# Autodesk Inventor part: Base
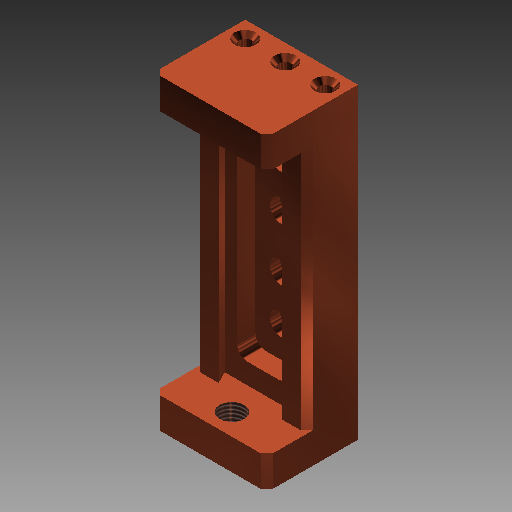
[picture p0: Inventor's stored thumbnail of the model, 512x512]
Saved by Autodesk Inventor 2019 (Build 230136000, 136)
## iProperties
Created: 2011-02
Part Number: Base
Material: Generic
Document SubType Name: Modeling
Designer: landrews
Density: 1 g/cm^3
Appearance: Copper - Polished
Mass: 182.26 g
Surface Area: 402.174 cm^2
Volume: 182.26 cm^3
Author: landrews
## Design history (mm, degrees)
sketch "Sketch1"
  geometry: L1 (-27.5, 12.5)-(27.5, 12.5); L2 (27.5, 12.5)-(27.5, 37.5); L3 (27.5, 37.5)-(15.5, 37.5); L4 (15.5, 37.5)-(18.5, 31.5); L5 (18.5, 31.5)-(-18.5, 31.5); L6 (-18.5, 31.5)-(-15.5, 37.5); L7 (-15.5, 37.5)-(-27.5, 37.5); L8 (-27.5, 37.5)-(-27.5, 12.5); L9 (0, 7.5)-(0, 42.5) reference; L10 (-38.5, 12.5)-(38.5, 12.5) reference; 2 further points
  constraints: 16 end point, 4 parallel, 2 equal length, 2 midpoint, 1 coincident, 1 collinear, 1 horizontal, 1 perpendicular, 1 other
  dimensions: "Base_Width" = 55 distance of L1.start L1.end; "Base_Height" = 25 distance of L1.end L2.end; "Slider_Shelf" = 12 distance of L2.end L3.end; "d3" = 9 horizontal distance of L2.end L4.end (computed from Slider_Shelf); "d2" = 6 distance between parallel lines of L3 L5
extrude "Extrusion1" new body sketch "Sketch1" taper "d8" = 0 deg; stored distance "Base_Length" = 120
sketch "Sketch4"
  geometry: L1 (11, -110)-(26, -110); L2 (31, -105)-(31, -15); L3 (26, -10)-(11, -10); L4 (6, -15)-(6, -105); L5 (-20, -60)-(57, -60) reference; L6 (18.5, 24)-(18.5, -144) reference; L7 (-9, -120)-(-9, 0) reference; L8 (37, 0)-(0, 0) reference; A1 r 5 centre (11, -105) between (6, -105) and (11, -110); A2 r 5 centre (26, -105) between (26, -110) and (31, -105); A3 r 5 centre (26, -15) between (31, -15) and (26, -10); A4 r 5 centre (11, -15) between (11, -10) and (6, -15)
  constraints: 8 end point, 8 point on circle, 8 tangent, 4 centre point, 3 equal radius, 2 parallel, 1 horizontal, 1 perpendicular, 2 other
  dimensions: "StopPlate_DP" = 5 radius of A1; "d25" = 100 distance between parallel lines of L1 L3 (computed from Base_Length); "d26" = 25 distance between parallel lines of L2 L4 (computed from Base_Width)
extrude "Extrusion2" cut sketch "Sketch4" extent not by distance; stored distance "d23" = 10; taper "d24" = 0 deg
sketch "Sketch6"
  geometry: L1 (27.5, 37.5)-(27.5, 12.5) reference; L2 (-27.5, 12.5)-(27.5, 12.5); L3 (27.5, 12.5)-(27.5, 57); L4 (27.5, 57)-(-27.5, 57); L5 (-27.5, 57)-(-27.5, 12.5); 1 further point
  constraints: 8 end point, 2 parallel, 1 horizontal, 1 perpendicular, 1 point on line
  dimensions: "EndBlock_HT" = 44.5 distance between parallel lines of L2 L4
extrude "Extrusion4" join sketch "Sketch6" taper "d38" = 0 deg; distance "EndBlock_DP" = 15
mirror "Mirror1"
sketch "Sketch7"
  geometry: L1 (-27.5, 57)-(27.5, 57) reference; L2 (0, 65.9)-(0, 3.6) reference; 2 further points
  constraints: 1 point on line
  dimensions: "d39" = 10.5 distance from line of point (0, 46.5) L1
hole "Hole1" sketch "Sketch7" at (0, 46.5) diameter "d40" = 12; stored, may be unused: countersink angle "d44" = 90 deg, drill point angle "d46" = 118 deg; dims "d41" = 6, "d42" = 4, "d43" = 2, "d45" = 8
sketch "Sketch14"
  geometry: L1 (27.5, 12.5)-(-27.5, 12.5) reference; L2 (0, 65.9)-(0, 3.6) reference; 2 further points
  constraints: 1 point on line
  dimensions: "d83" = 8 distance from line of L1 point (0, 20.5)
hole "Hole5" sketch "Sketch14" at (0, 20.5) diameter "d84" = 6; stored, may be unused: countersink angle "d88" = 90 deg, drill point angle "d90" = 118 deg; dims "d85" = 6, "d86" = 10.4, "d87" = 2, "d89" = 15 (= EndBlock_DP)
sketch "Sketch9"
  geometry: C1 r 5.2 at (0, 20.5) reference; 2 further points
  constraints: 1 coincident
hole "Hole3" sketch "Sketch9" at (0, 20.5) diameter "d62" = 4.134; stored, may be unused: countersink angle "d66" = 90 deg, drill point angle "d68" = 118 deg; dims "d63" = 6, "d64" = 10.4, "d65" = 2, "d67" = 8
pattern_linear "Rectangular Pattern2" dims "d71" = 19.5
mirror "Mirror2"
sketch "Sketch11"
  geometry: L1 (0, 0)-(55, 0) reference; L2 (0, -44.5)-(0, 0) reference; L3 (55, 0)-(55, -44.5) reference; 3 further points
  constraints: 1 horizontal alignment
  dimensions: "d103" = 9 distance from line of L1 point (10, -9); "d104" = 10 distance from line of L2 point (10, -9) (= d105); "d105" = 10 distance from line of L3 point (45, -9)
hole "Hole6" sketch "Sketch11" at (10, -9), (45, -9) diameter "d91" = 4.134; stored, may be unused: countersink angle "d95" = 90 deg, drill point angle "d97" = 118 deg; dims "d92" = 6, "d93" = 4, "d94" = 2, "d96" = 10
thread "Thread1" dims "d98" = 10, "d99" = 0
chamfer "Chamfer1" distance "d100" = 3; stored, may be unused: second distance "d101" = 2, angle "d102" = 45 deg
sketch "Sketch17"
  geometry: L1 (35, 25)-(20, 25) reference; L2 (15, 30)-(15, 120) reference; L3 (20, 125)-(35, 125) reference; L4 (40, 120)-(40, 30) reference; L5 (0, 150)-(0, 0) reference; L6 (0, 0)-(55, 0) reference; L7 (55, 0)-(55, 150) reference; L8 (0, 150)-(55, 150) reference; A1 r 5 centre (35, 30) between (35, 25) and (40, 30) reference; A2 r 5 centre (20, 30) between (15, 30) and (20, 25) reference; A3 r 5 centre (20, 120) between (20, 125) and (15, 120) reference; A4 r 5 centre (35, 120) between (40, 120) and (35, 125) reference; 1 further point
extrude "Extrusion7" join sketch "Sketch17" distance "d111" = 10; taper "d112" = 0 deg
sketch "Sketch18"
  geometry: L1 (-15, 120)-(-15, 30) reference; L2 (-20, 25)-(-35, 25) reference; L3 (-35, 125)-(-20, 125) reference; 5 further points
  dimensions: "d113" = 12.5 distance from line of L1 point (-27.5, 110); "d114" = 12.5 distance from line of L1 point (-27.5, 40); "d115" = 15 distance from line of L2 point (-27.5, 40); "d116" = 15 distance from line of L3 point (-27.5, 110) (= d115); "d117" = 22 distance of point (-27.5, 110) point (-27.5, 88) (= d118); "d118" = 22 distance of point (-27.5, 40) point (-27.5, 62); "d119" = 12.5 distance from line of L1 point (-27.5, 62); "d120" = 12.5 distance from line of L1 point (-27.5, 88)
hole "Hole7" sketch "Sketch18" at (-27.5, 110), (-27.5, 40), (-27.5, 88), (-27.5, 62) diameter "d121" = 6; stored, may be unused: countersink angle "d125" = 90 deg, drill point angle "d127" = 118 deg; dims "d122" = 6, "d123" = 11, "d124" = 5, "d126" = 8
body "Solid1"
node "Projected Loop1"
other parameters: "d106" = 0
